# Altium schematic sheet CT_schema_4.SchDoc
size 362 x 192 mm
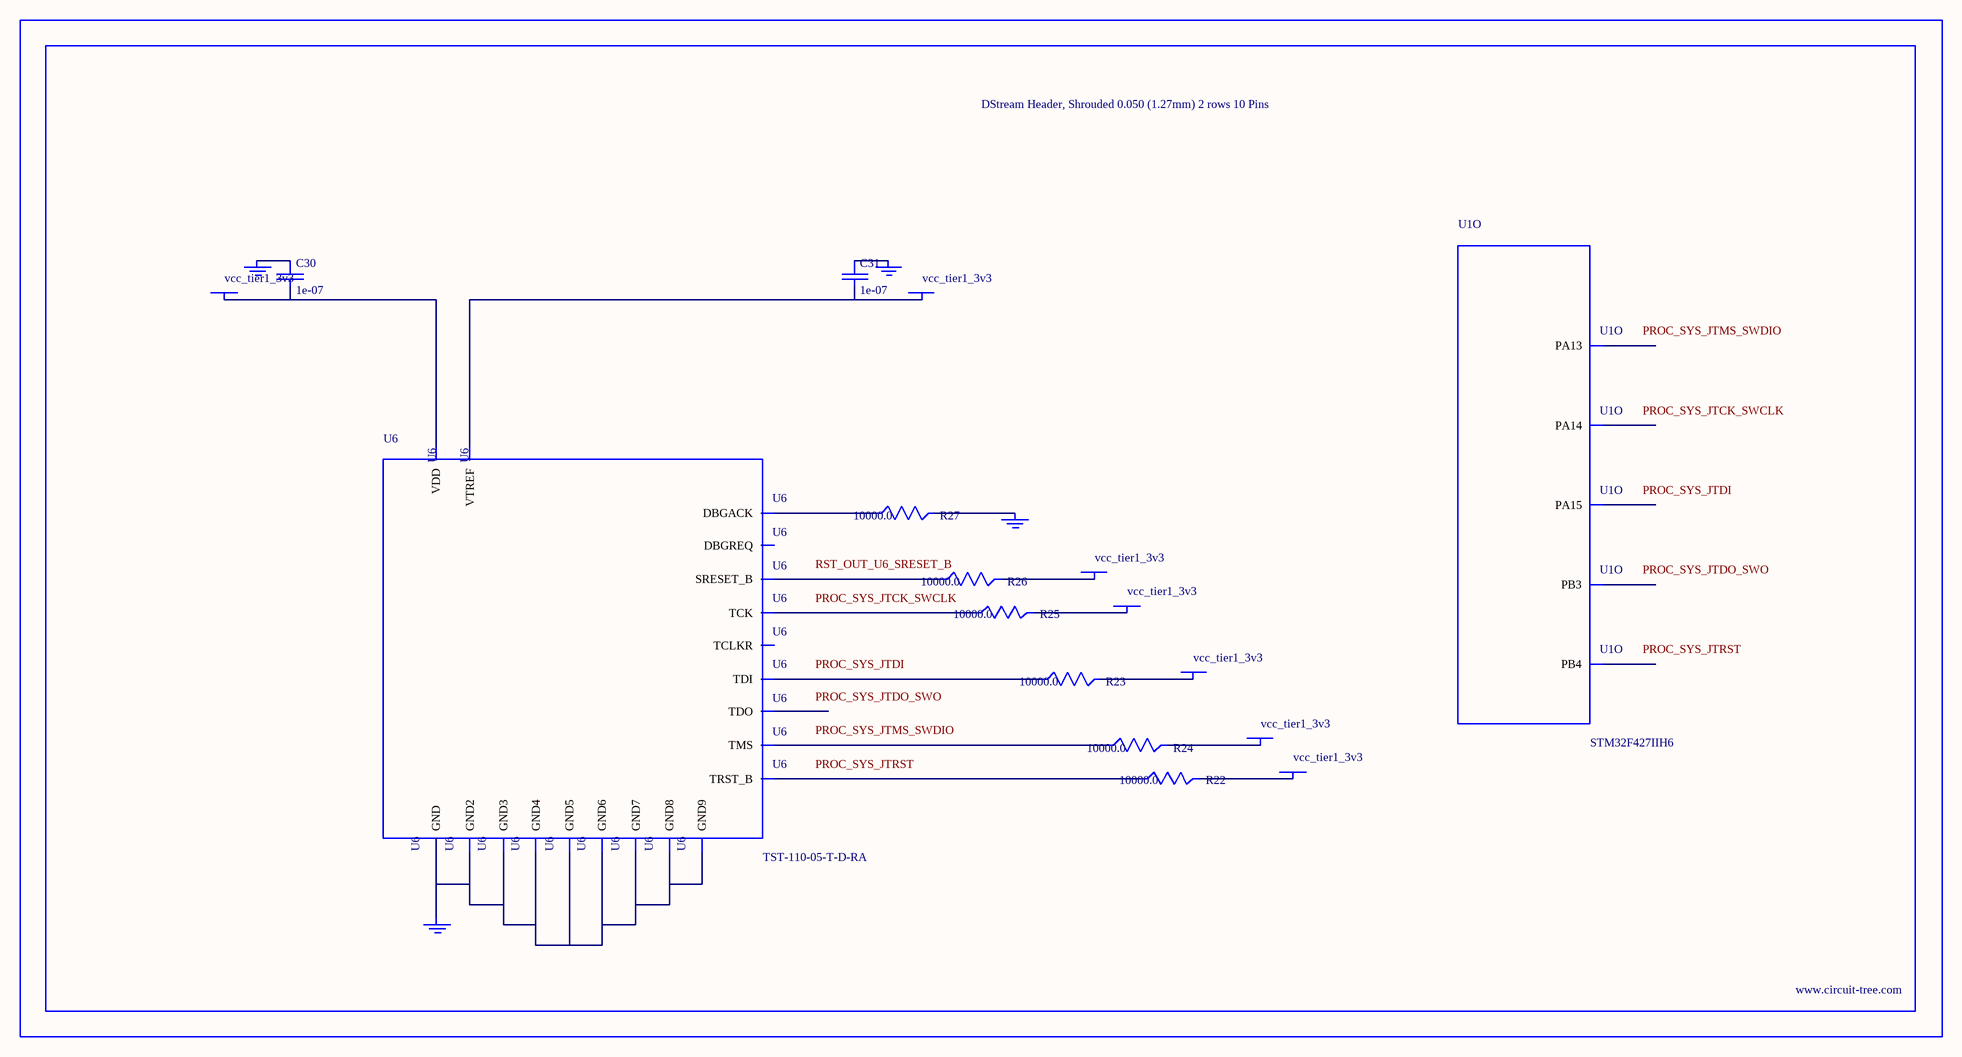
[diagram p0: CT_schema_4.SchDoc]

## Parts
BORDER3  (no value)
C30  1e-07  [C0402]
C31  1e-07  [C0402]
GND_INSTANCE_3_0  (no value)
GND_INSTANCE_3_1  (no value)
GND_INSTANCE_3_2  (no value)
GND_INSTANCE_3_3  (no value)
POWER_INSTANCE_3_0  vcc_tier1_3v3
POWER_INSTANCE_3_1  vcc_tier1_3v3
POWER_INSTANCE_3_2  vcc_tier1_3v3
POWER_INSTANCE_3_3  vcc_tier1_3v3
POWER_INSTANCE_3_4  vcc_tier1_3v3
POWER_INSTANCE_3_5  vcc_tier1_3v3
POWER_INSTANCE_3_6  vcc_tier1_3v3
R22  10000.0  [R0603]
R23  10000.0  [R0603]
R24  10000.0  [R0603]
R25  10000.0  [R0603]
R26  10000.0  [R0603]
R27  10000.0  [R0603]
U1  STM32F427IIH6  [UFBGA176_25]  (part O of 17)
U6  TST-110-05-T-D-RA  [TST-110-05-T-D-RA]

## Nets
NetC30_1: C30.1 GND_INSTANCE_3_1.0(GND)
NetC30_2: C30.2 POWER_INSTANCE_3_1.0(PWR) U6.2(VDD)
NetC31_1: C31.1 GND_INSTANCE_3_0.0(GND)
NetC31_2: C31.2 POWER_INSTANCE_3_0.0(PWR) U6.1(VTREF)
NetGND_INSTANCE_3_2_0: GND_INSTANCE_3_2.0(GND) R27.2
NetGND_INSTANCE_3_3_0: GND_INSTANCE_3_3.0(GND) U6.4(GND) U6.6(GND2) U6.8(GND3) U6.10(GND4) U6.12(GND5) U6.14(GND6) U6.16(GND7) U6.18(GND8) U6.20(GND9)
NetPOWER_INSTANCE_3_2_0: POWER_INSTANCE_3_2.0(PWR) R22.2
NetPOWER_INSTANCE_3_3_0: POWER_INSTANCE_3_3.0(PWR) R23.2
NetPOWER_INSTANCE_3_4_0: POWER_INSTANCE_3_4.0(PWR) R24.2
NetPOWER_INSTANCE_3_5_0: POWER_INSTANCE_3_5.0(PWR) R25.2
NetPOWER_INSTANCE_3_6_0: POWER_INSTANCE_3_6.0(PWR) R26.2
NetR22_1: R22.1 U6.3(TRST_B)
NetR23_1: R23.1 U6.5(TDI)
NetR24_1: R24.1 U6.7(TMS)
NetR25_1: R25.1 U6.9(TCK)
NetR26_1: R26.1 U6.15(SRESET_B)
NetR27_1: R27.1 U6.19(DBGACK)

Not connected (* = marked no-connect by the designer): U1 A9(PB4) A10(PB3) A13(PA15) A14(PA14) A15(PA13); U6 11(TCLKR) 13(TDO) 17(DBGREQ)

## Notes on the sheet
- Labels drawn without touching a wire or pin: PROC_SYS_JTCK_SWCLK, PROC_SYS_JTDI, PROC_SYS_JTDO_SWO, PROC_SYS_JTMS_SWDIO, PROC_SYS_JTRST, RST_OUT_U6_SRESET_B

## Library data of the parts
BORDER3 = BORDER_PAGE3
C30 C31 = C0402C104K3RACTU
GND_INSTANCE_3_0-GND_INSTANCE_3_3 = GND
POWER_INSTANCE_3_0-POWER_INSTANCE_3_6 = PWR
R22-R27 = RC0603JR-0710KL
